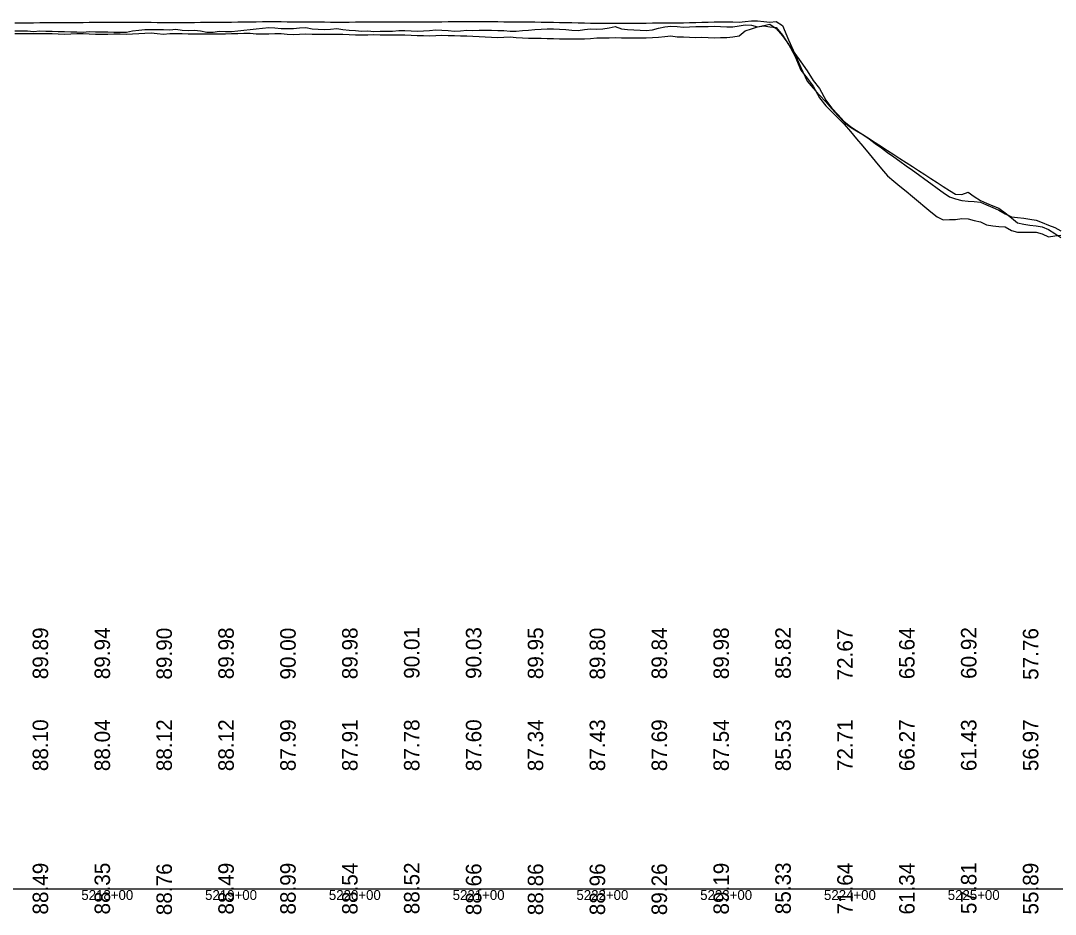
# Model space of a CAD drawing. Extents: x 2147288 to 2220488, y 740833 to 759333.
# Drawn here: x 2204108 to 2204944, y 750063 to 750784 of the extents above; entities that cross this region are included whole.
import ezdxf

# ---------------------------------------------------------------- set-up
doc = ezdxf.new("R2010")
doc.units = 0
for name, color, linetype in [('RD_DDB_Profile_EX', 7, 'Continuous'), ('RD_DDB_StaTX', 7, 'Continuous'), ('RD_DDB_StripGrade', 7, 'Continuous'), ('RD_GPK_Profile_Cell', 7, 'Continuous')]:
    doc.layers.add(name, color=color, linetype=linetype)

msp = doc.modelspace()

# ---------------------------------------------------------------- linework, layer by layer
at = {"layer": 'RD_DDB_Profile_EX'}
for points in [[(2204103.28, 750782.55), (2204108.28, 750782.61), (2204113.28, 750782.66), (2204118.28, 750782.71), (2204123.28, 750782.77), (2204128.28, 750782.83), (2204133.28, 750782.89), (2204138.28, 750782.92), (2204143.28, 750782.92), (2204148.28, 750782.92), (2204153.28, 750782.91), (2204158.28, 750782.97), (2204163.28, 750783.03), (2204168.28, 750783.09), (2204173.28, 750783.13), (2204178.28, 750783.12), (2204183.28, 750783.09), (2204188.28, 750783.06), (2204193.28, 750783.02), (2204198.28, 750783.03), (2204203.28, 750783.04), (2204208.28, 750783.06), (2204213.28, 750783.04), (2204218.28, 750783), (2204223.28, 750782.97), (2204228.28, 750782.94), (2204233.28, 750782.96), (2204238.28, 750782.98), (2204243.28, 750782.97), (2204248.28, 750783.01), (2204253.28, 750783.08), (2204258.28, 750783.15), (2204263.28, 750783.21), (2204268.28, 750783.22), (2204273.28, 750783.22), (2204278.28, 750783.27), (2204283.28, 750783.34), (2204288.28, 750783.4), (2204293.28, 750783.47), (2204298.28, 750783.5), (2204303.28, 750783.55), (2204308.28, 750783.57), (2204313.28, 750783.59), (2204318.28, 750783.55), (2204323.28, 750783.51), (2204328.28, 750783.47), (2204333.28, 750783.43), (2204338.28, 750783.4), (2204343.28, 750783.37), (2204348.28, 750783.33), (2204353.28, 750783.29), (2204358.28, 750783.25), (2204363.28, 750783.21), (2204368.28, 750783.22), (2204373.28, 750783.26), (2204378.28, 750783.29), (2204383.28, 750783.33), (2204388.28, 750783.36), (2204393.28, 750783.39), (2204398.28, 750783.42), (2204403.28, 750783.43), (2204408.28, 750783.44), (2204413.28, 750783.44), (2204418.28, 750783.43), (2204423.28, 750783.43), (2204428.28, 750783.44), (2204433.28, 750783.47), (2204438.28, 750783.49), (2204443.28, 750783.52), (2204448.28, 750783.54), (2204453.28, 750783.56), (2204458.28, 750783.57), (2204463.28, 750783.56), (2204468.28, 750783.56), (2204473.28, 750783.56), (2204478.28, 750783.57), (2204483.28, 750783.57), (2204488.28, 750783.57), (2204493.28, 750783.56), (2204498.28, 750783.52), (2204503.28, 750783.46), (2204508.28, 750783.4), (2204513.28, 750783.34), (2204518.28, 750783.31), (2204523.28, 750783.29), (2204528.28, 750783.24), (2204533.28, 750783.16), (2204538.28, 750783.06)], [(2204538.28, 750783.06), (2204543.28, 750782.96), (2204548.28, 750782.86), (2204553.28, 750782.76), (2204558.28, 750782.66), (2204563.28, 750782.57), (2204568.28, 750782.47), (2204573.28, 750782.44), (2204578.28, 750782.44), (2204583.28, 750782.44), (2204588.28, 750782.45), (2204593.28, 750782.43), (2204598.28, 750782.38), (2204603.28, 750782.34), (2204608.28, 750782.34), (2204613.28, 750782.42), (2204618.28, 750782.56), (2204623.28, 750782.64), (2204628.28, 750782.65), (2204633.28, 750782.64), (2204638.28, 750782.67), (2204643.28, 750782.72), (2204648.28, 750782.88), (2204653.28, 750783), (2204658.28, 750783.13), (2204663.28, 750783.27), (2204668.28, 750783.35), (2204673.28, 750783.39), (2204678.28, 750783.35), (2204683.28, 750783.29), (2204688.28, 750783.23), (2204693.28, 750783.59), (2204698.28, 750784.19), (2204703.28, 750784.33), (2204708.28, 750783.65), (2204713.28, 750783.23), (2204718.28, 750783.66), (2204723.28, 750780.55), (2204728.28, 750768.93), (2204733.28, 750757.46), (2204738.28, 750746.62), (2204743.28, 750735.54), (2204748.28, 750729.84), (2204753.28, 750724.3), (2204758.28, 750718.75), (2204763.28, 750713.17), (2204768.28, 750707.55), (2204773.28, 750702.31), (2204778.28, 750698.44), (2204783.28, 750695.47), (2204788.28, 750692.44), (2204793.28, 750688.84), (2204798.28, 750685.24), (2204803.28, 750681.63), (2204808.28, 750678.03), (2204813.28, 750674.43), (2204818.28, 750670.83), (2204823.28, 750667.23), (2204828.28, 750663.62), (2204833.28, 750660.02), (2204838.28, 750656.42), (2204843.28, 750652.82), (2204848.28, 750649.21), (2204853.28, 750645.61), (2204858.28, 750642.01), (2204863.28, 750640.5), (2204868.28, 750639.1), (2204873.28, 750638.66), (2204878.28, 750638.46), (2204883.28, 750637.69), (2204888.28, 750635.58), (2204893.28, 750633.47), (2204898.28, 750631.36), (2204903.28, 750628.37), (2204908.28, 750625.98), (2204913.28, 750625.38), (2204918.28, 750624.79), (2204923.28, 750624.17), (2204928.28, 750623.36), (2204933.28, 750621.34), (2204938.28, 750619.32), (2204943.28, 750617.3), (2204948.28, 750614.78)], [(2204538.28, 750777.85), (2204543.28, 750777.43), (2204548.28, 750777.16), (2204553.28, 750776.75), (2204558.28, 750776.41), (2204563.28, 750777.34), (2204568.28, 750777.72), (2204573.28, 750777.51), (2204578.28, 750777.82), (2204583.28, 750778.56), (2204588.28, 750779.62), (2204593.28, 750777.89), (2204598.28, 750777.15), (2204603.28, 750777.03), (2204608.28, 750776.67), (2204613.28, 750776.53), (2204618.28, 750776.87), (2204623.28, 750778.28), (2204628.28, 750779.41), (2204633.28, 750780), (2204638.28, 750779.55), (2204643.28, 750779.14), (2204648.28, 750779.44), (2204653.28, 750779.61), (2204658.28, 750779.55), (2204663.28, 750779.73), (2204668.28, 750780), (2204673.28, 750779.66), (2204678.28, 750779.33), (2204683.28, 750779.45), (2204688.28, 750780.28), (2204693.28, 750780.98), (2204698.28, 750780.72), (2204703.28, 750779.41), (2204708.28, 750780.58), (2204713.28, 750781.45), (2204718.28, 750778.07), (2204723.28, 750771.98), (2204728.28, 750765.35), (2204733.28, 750755.95), (2204738.28, 750744.48), (2204743.28, 750738.02), (2204748.28, 750731.34), (2204753.28, 750722.01), (2204758.28, 750715.47), (2204763.28, 750710.65), (2204768.28, 750705.76), (2204773.28, 750700.83), (2204778.28, 750694.98), (2204783.28, 750688.98), (2204788.28, 750682.99), (2204793.28, 750676.95), (2204798.28, 750670.81), (2204803.28, 750664.68), (2204808.28, 750659.03), (2204813.28, 750654.89), (2204818.28, 750650.75), (2204823.28, 750646.61), (2204828.28, 750642.47), (2204833.28, 750638.33), (2204838.28, 750634.18), (2204843.28, 750630.04), (2204848.28, 750625.9), (2204853.28, 750623.6), (2204858.28, 750623.73), (2204863.28, 750623.86), (2204868.28, 750624.63), (2204873.28, 750624.27), (2204878.28, 750623.13), (2204883.28, 750622), (2204888.28, 750619.46), (2204893.28, 750618.68), (2204898.28, 750618.3), (2204903.28, 750617.92), (2204908.28, 750615.02), (2204913.28, 750613.64), (2204918.28, 750613.54), (2204923.28, 750613.61), (2204928.28, 750613.69), (2204933.28, 750612.25), (2204938.28, 750609.93), (2204943.28, 750610.51), (2204948.28, 750611.09)], [(2204103.28, 750776.07), (2204108.28, 750776.24), (2204113.28, 750776.18), (2204118.28, 750775.74), (2204123.28, 750776.07), (2204128.28, 750775.98), (2204133.28, 750775.81), (2204138.28, 750775.63), (2204143.28, 750775.62), (2204148.28, 750775.45), (2204153.28, 750775.35), (2204158.28, 750775.11), (2204163.28, 750775.53), (2204168.28, 750775.41), (2204173.28, 750775.25), (2204178.28, 750775.27), (2204183.28, 750775.12), (2204188.28, 750774.94), (2204193.28, 750775.03), (2204198.28, 750776.15), (2204203.28, 750776.61), (2204208.28, 750777.18), (2204213.28, 750777.13), (2204218.28, 750777.21), (2204223.28, 750777.2), (2204228.28, 750777.07), (2204233.28, 750777.39), (2204238.28, 750776.71), (2204243.28, 750776.49), (2204248.28, 750776.57), (2204253.28, 750776.22), (2204258.28, 750775.16), (2204263.28, 750774.99), (2204268.28, 750775.84), (2204273.28, 750775.5), (2204278.28, 750775.66), (2204283.28, 750776.03), (2204288.28, 750776.67), (2204293.28, 750777.25), (2204298.28, 750777.83), (2204303.28, 750778.31), (2204308.28, 750778.79), (2204313.28, 750778.5), (2204318.28, 750777.95), (2204323.28, 750778.12), (2204328.28, 750778), (2204333.28, 750778.7), (2204338.28, 750778.79), (2204343.28, 750777.7), (2204348.28, 750777.37), (2204353.28, 750777.16), (2204358.28, 750777.61), (2204363.28, 750778.06), (2204368.28, 750777.19), (2204373.28, 750776.62), (2204378.28, 750776.3), (2204383.28, 750775.96), (2204388.28, 750776.03), (2204393.28, 750775.72), (2204398.28, 750775.85), (2204403.28, 750775.91), (2204408.28, 750775.78), (2204413.28, 750776.47), (2204418.28, 750776.45), (2204423.28, 750776.03), (2204428.28, 750775.96), (2204433.28, 750776.06), (2204438.28, 750776.35), (2204443.28, 750776.84), (2204448.28, 750776.79), (2204453.28, 750776.36), (2204458.28, 750775.98), (2204463.28, 750776.22), (2204468.28, 750776.67), (2204473.28, 750776.54), (2204478.28, 750776.76), (2204483.28, 750776.7), (2204488.28, 750776.67), (2204493.28, 750776.49), (2204498.28, 750776.34), (2204503.28, 750775.82), (2204508.28, 750775.8), (2204513.28, 750776.54), (2204518.28, 750776.73), (2204523.28, 750777.3), (2204528.28, 750777.51), (2204533.28, 750777.86), (2204538.28, 750777.85)], [(2204103.28, 750773.91), (2204108.28, 750773.87), (2204113.28, 750773.87), (2204118.28, 750773.98), (2204123.28, 750774.02), (2204128.28, 750774.01), (2204133.28, 750773.89), (2204138.28, 750773.71), (2204143.28, 750773.56), (2204148.28, 750773.7), (2204153.28, 750774.02), (2204158.28, 750773.89), (2204163.28, 750773.72), (2204168.28, 750773.36), (2204173.28, 750773.44), (2204178.28, 750773.56), (2204183.28, 750773.68), (2204188.28, 750773.7), (2204193.28, 750773.33), (2204198.28, 750773.63), (2204203.28, 750774.11), (2204208.28, 750774.35), (2204213.28, 750774.58), (2204218.28, 750774.04), (2204223.28, 750773.53), (2204228.28, 750773.9), (2204233.28, 750774.08), (2204238.28, 750773.93), (2204243.28, 750773.82), (2204248.28, 750773.77), (2204253.28, 750773.74), (2204258.28, 750773.71), (2204263.28, 750773.7), (2204268.28, 750773.76), (2204273.28, 750773.84), (2204278.28, 750773.96), (2204283.28, 750774.05), (2204288.28, 750774.27), (2204293.28, 750774.15), (2204298.28, 750773.71), (2204303.28, 750773.72), (2204308.28, 750773.86), (2204313.28, 750773.97), (2204318.28, 750774), (2204323.28, 750773.52), (2204328.28, 750773.18), (2204333.28, 750773.56), (2204338.28, 750773.74), (2204343.28, 750773.54), (2204348.28, 750773.4), (2204353.28, 750773.47), (2204358.28, 750773.5), (2204363.28, 750773.53), (2204368.28, 750773.53), (2204373.28, 750773.15), (2204378.28, 750772.97), (2204383.28, 750772.95), (2204388.28, 750773), (2204393.28, 750773.09), (2204398.28, 750773.02), (2204403.28, 750772.9), (2204408.28, 750772.87), (2204413.28, 750772.95), (2204418.28, 750772.79), (2204423.28, 750772.54), (2204428.28, 750772.32), (2204433.28, 750772.31), (2204438.28, 750772.24), (2204443.28, 750772.39), (2204448.28, 750772.54), (2204453.28, 750772.5), (2204458.28, 750772.35), (2204463.28, 750772.22), (2204468.28, 750771.99), (2204473.28, 750771.73), (2204478.28, 750771.52), (2204483.28, 750771.34), (2204488.28, 750771.07), (2204493.28, 750770.89), (2204498.28, 750771.13), (2204503.28, 750771.28), (2204508.28, 750770.86), (2204513.28, 750770.54), (2204518.28, 750770.22), (2204523.28, 750770.13), (2204528.28, 750770.26), (2204533.28, 750770.02), (2204538.28, 750769.84)], [(2204538.28, 750769.84), (2204543.28, 750769.78), (2204548.28, 750769.72), (2204553.28, 750769.79), (2204558.28, 750769.73), (2204563.28, 750769.62), (2204568.28, 750770.08), (2204573.28, 750770.47), (2204578.28, 750770.53), (2204583.28, 750770.6), (2204588.28, 750770.64), (2204593.28, 750770.62), (2204598.28, 750770.54), (2204603.28, 750770.4), (2204608.28, 750770.4), (2204613.28, 750770.52), (2204618.28, 750770.67), (2204623.28, 750770.91), (2204628.28, 750771.59), (2204633.28, 750772.11), (2204638.28, 750771.34), (2204643.28, 750771.2), (2204648.28, 750771.06), (2204653.28, 750770.84), (2204658.28, 750770.99), (2204663.28, 750770.8), (2204668.28, 750770.61), (2204673.28, 750770.84), (2204678.28, 750770.85), (2204683.28, 750771.35), (2204688.28, 750772), (2204693.28, 750776.15), (2204698.28, 750777.76), (2204703.28, 750779.49), (2204708.28, 750780.22), (2204713.28, 750779.47), (2204718.28, 750778.72), (2204723.28, 750772.63), (2204728.28, 750765.09), (2204733.28, 750757.91), (2204738.28, 750751.25), (2204743.28, 750743.77), (2204748.28, 750736.15), (2204753.28, 750729.48), (2204758.28, 750720.14), (2204763.28, 750713.78), (2204768.28, 750708.25), (2204773.28, 750702.85), (2204778.28, 750698.78), (2204783.28, 750695.55), (2204788.28, 750692.32), (2204793.28, 750689.1), (2204798.28, 750685.89), (2204803.28, 750682.67), (2204808.28, 750679.46), (2204813.28, 750676.24), (2204818.28, 750673.03), (2204823.28, 750669.81), (2204828.28, 750666.6), (2204833.28, 750663.38), (2204838.28, 750660.17), (2204843.28, 750656.95), (2204848.28, 750653.74), (2204853.28, 750650.48), (2204858.28, 750647.32), (2204863.28, 750644.37), (2204868.28, 750644.13), (2204873.28, 750645.84), (2204878.28, 750642.35), (2204883.28, 750639.19), (2204888.28, 750637.08), (2204893.28, 750634.97), (2204898.28, 750632.86), (2204903.28, 750629.13), (2204908.28, 750625.19), (2204913.28, 750621.25), (2204918.28, 750619.96), (2204923.28, 750619.29), (2204928.28, 750618.63), (2204933.28, 750617.96), (2204938.28, 750615.82), (2204943.28, 750612.58), (2204948.28, 750609.33)]]:
    msp.add_lwpolyline(points, dxfattribs=at)
at = {"layer": 'RD_GPK_Profile_Cell'}
msp.add_line((2198888.28, 750083.43), (2220488.28, 750083.43), dxfattribs=at)

# ---------------------------------------------------------------- texts
at = {"layer": 'RD_DDB_Profile_EX'}
for s, p in [('89.89', (2204130.08, 750252.64)), ('89.94', (2204180.08, 750252.66)), ('89.90', (2204230.08, 750252.38)), ('89.98', (2204280.08, 750252.64)), ('90.00', (2204330.08, 750252.38)), ('89.98', (2204380.08, 750252.64)), ('90.01', (2204430.08, 750253)), ('90.03', (2204480.08, 750252.89)), ('89.95', (2204530.08, 750252.69)), ('89.80', (2204580.08, 750252.38)), ('89.84', (2204630.08, 750252.66)), ('89.98', (2204680.08, 750252.64)), ('85.82', (2204730.08, 750252.89)), ('72.67', (2204780.08, 750251.67)), ('65.64', (2204830.08, 750252.66)), ('60.92', (2204880.08, 750252.89)), ('57.76', (2204930.08, 750252.13)), ('88.49', (2204130.08, 750062.64)), ('88.35', (2204180.08, 750062.69)), ('88.76', (2204230.08, 750062.13)), ('88.49', (2204280.08, 750062.64)), ('88.99', (2204330.08, 750062.64)), ('88.54', (2204380.08, 750062.66)), ('88.52', (2204430.08, 750062.89)), ('88.66', (2204480.08, 750062.13)), ('88.86', (2204530.08, 750062.13)), ('88.96', (2204580.08, 750062.13)), ('89.26', (2204630.08, 750062.13)), ('89.19', (2204680.08, 750062.64)), ('85.33', (2204730.08, 750062.89)), ('71.64', (2204780.08, 750062.66)), ('61.34', (2204830.08, 750062.66)), ('57.81', (2204880.08, 750063)), ('55.89', (2204930.08, 750062.64))]:
    msp.add_text(s, height=12.5, rotation=90, dxfattribs=at).set_placement(p)
at = {"layer": 'RD_DDB_StaTX'}
for s, p in [('5218+00', (2204156.88, 750074.43)), ('5218+00', (2204156.88, 750074.43)), ('5218+00', (2204156.88, 750074.43)), ('5219+00', (2204256.88, 750074.43)), ('5219+00', (2204256.88, 750074.43)), ('5219+00', (2204256.88, 750074.43)), ('5220+00', (2204356.88, 750074.43)), ('5220+00', (2204356.88, 750074.43)), ('5220+00', (2204356.88, 750074.43)), ('5221+00', (2204456.88, 750074.43)), ('5221+00', (2204456.88, 750074.43)), ('5221+00', (2204456.88, 750074.43)), ('5222+00', (2204556.88, 750074.43)), ('5222+00', (2204556.88, 750074.43)), ('5222+00', (2204556.88, 750074.43)), ('5223+00', (2204656.88, 750074.43)), ('5223+00', (2204656.88, 750074.43)), ('5223+00', (2204656.88, 750074.43)), ('5224+00', (2204756.88, 750074.43)), ('5224+00', (2204756.88, 750074.43)), ('5224+00', (2204756.88, 750074.43)), ('5225+00', (2204856.88, 750074.43)), ('5225+00', (2204856.88, 750074.43)), ('5225+00', (2204856.88, 750074.43))]:
    msp.add_text(s, height=8, dxfattribs=at).set_placement(p)
at = {"layer": 'RD_DDB_StripGrade'}
for s, p in [('88.10', (2204130.08, 750178.43)), ('88.04', (2204180.08, 750178.43)), ('88.12', (2204230.08, 750178.43)), ('88.12', (2204280.08, 750178.43)), ('87.99', (2204330.08, 750178.43)), ('87.91', (2204380.08, 750178.43)), ('87.78', (2204430.08, 750178.43)), ('87.60', (2204480.08, 750178.43)), ('87.34', (2204530.08, 750178.43)), ('87.43', (2204580.08, 750178.43)), ('87.69', (2204630.08, 750178.43)), ('87.54', (2204680.08, 750178.43)), ('85.53', (2204730.08, 750178.43)), ('72.71', (2204780.08, 750178.43)), ('66.27', (2204830.08, 750178.43)), ('61.43', (2204880.08, 750178.43)), ('56.97', (2204930.08, 750178.43))]:
    msp.add_text(s, height=12.5, rotation=90, dxfattribs=at).set_placement(p)

doc.saveas('drawing.dxf')
